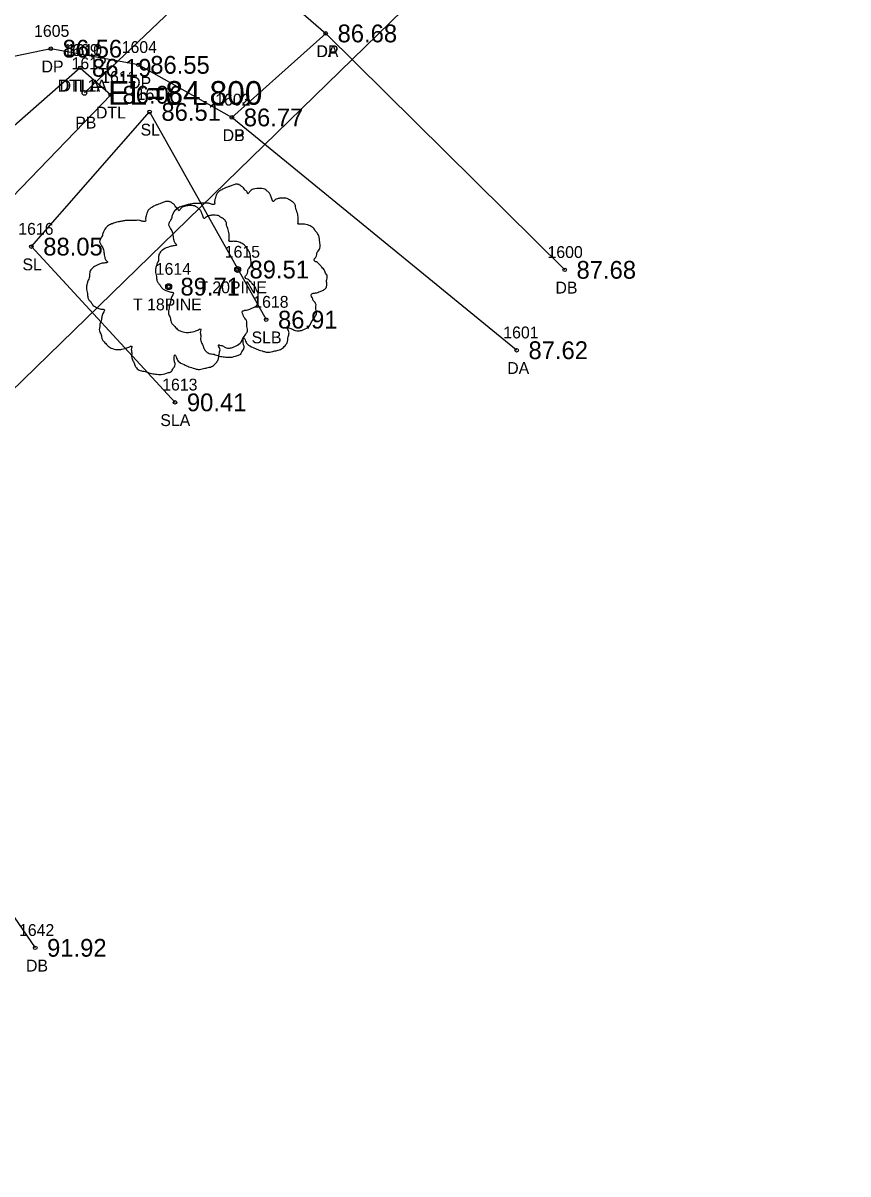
# Model space of a CAD drawing. Extents: x 2500794 to 2511032, y 910653 to 917533.
# Drawn here: x 2504844.2 to 2504913.8, y 912430.5 to 912527.6 of the extents above; entities that cross this region are included whole.
import ezdxf

# ---------------------------------------------------------------- set-up
doc = ezdxf.new("R2010")
doc.units = 0
for name, color, linetype in [('RD_EX_DR_Pipe', 7, 'Continuous'), ('RD_EX_DR_Pipe_txCode', 7, 'Continuous'), ('RD_EX_Driveway', 7, 'Continuous'), ('RD_EX_Driveway_txCode', 7, 'Continuous'), ('RD_EX_H2O_txCode', 7, 'Continuous'), ('RD_EX_RW', 7, 'Continuous'), ('RD_EX_TX_Driveway_ELEV', 7, 'Continuous'), ('RD_EX_TX_H2O_ELEV', 7, 'Continuous'), ('RD_EX_TX_VEG_ELEV', 7, 'Continuous'), ('RD_EX_VEG', 7, 'Continuous'), ('RD_EX_VEG_txCode', 7, 'Continuous'), ('RD_SMD_Locator', 7, 'Continuous'), ('RD_TX_Pipe_ElevEX', 7, 'Continuous')]:
    doc.layers.add(name, color=color, linetype=linetype)

msp = doc.modelspace()

# ---------------------------------------------------------------- linework, layer by layer
at = {"layer": 'RD_EX_DR_Pipe'}
msp.add_line((2504864.709, 912536.271), (2504849.414, 912521.689), dxfattribs=at)
at = {"layer": 'RD_EX_Driveway'}
for p, q in [((2504869.768, 912526.71), (2504889.926, 912506.766)), ((2504885.872, 912499.982), (2504861.854, 912519.624)), ((2504835.044, 912464.414), (2504845.262, 912449.566))]:
    msp.add_line(p, q, dxfattribs=at)
msp.add_lwpolyline([(2504858.984, 912543.75), (2504859.029, 912538.328), (2504862.415, 912533.12), (2504869.768, 912526.71), (2504861.854, 912519.624), (2504853.965, 912524.059), (2504846.572, 912525.423), (2504838.286, 912523.698)], dxfattribs=at)
at = {"layer": 'RD_EX_H2O_txCode'}
msp.add_line((2504849.048, 912523.81), (2504814.012, 912493.075), dxfattribs=at)
msp.add_lwpolyline([(2504849.048, 912523.81), (2504851.627, 912521.534), (2504818.417, 912487.12), (2504814.012, 912493.075)], dxfattribs=at)
at = {"layer": 'RD_EX_RW'}
msp.add_line((2503981.182, 911658.034), (2505252.676, 912894.806), dxfattribs=at)
at = {"layer": 'RD_EX_VEG'}
msp.add_lwpolyline([(2504857.057, 912495.585), (2504844.938, 912508.724), (2504854.906, 912520.09), (2504864.743, 912502.565)], dxfattribs=at)
for centre, radius in [((2504862.337, 912506.79), 0.25), ((2504862.325, 912506.771), 0.0001), ((2504856.515, 912505.346), 0.25), ((2504856.502, 912505.327), 0.0001)]:
    msp.add_circle(centre, radius, dxfattribs=at)
for points in [[(2504862.469, 912513.958), (2504862.169, 912513.983), (2504861.844, 912513.883), (2504861.595, 912513.783), (2504861.37, 912513.708), (2504861.145, 912513.608), (2504860.845, 912513.433), (2504860.62, 912513.233), (2504860.495, 912512.983), (2504860.445, 912512.758), (2504860.395, 912512.483), (2504860.395, 912512.308), (2504860.27, 912512.283), (2504860.12, 912512.308), (2504859.87, 912512.383), (2504859.62, 912512.383), (2504859.37, 912512.383), (2504859.021, 912512.358), (2504858.671, 912512.358), (2504858.396, 912512.308), (2504858.071, 912512.258), (2504857.696, 912512.133), (2504857.346, 912512.008), (2504857.047, 912511.758), (2504856.797, 912511.284), (2504856.672, 912510.934), (2504856.522, 912510.684), (2504856.672, 912510.234), (2504856.847, 912509.884), (2504856.872, 912509.684), (2504856.947, 912509.26), (2504857.047, 912509.035), (2504857.171, 912508.835), (2504857.097, 912508.81), (2504856.722, 912508.76), (2504856.422, 912508.66), (2504855.997, 912508.435), (2504855.772, 912508.21), (2504855.672, 912507.885), (2504855.647, 912507.535), (2504855.547, 912507.335), (2504855.472, 912507.061), (2504855.447, 912506.986), (2504855.397, 912506.661), (2504855.497, 912506.211), (2504855.522, 912505.861), (2504855.647, 912505.636), (2504855.797, 912505.461), (2504855.972, 912505.211), (2504856.372, 912504.986), (2504856.697, 912504.886), (2504856.897, 912504.862), (2504856.722, 912504.362), (2504856.672, 912504.012), (2504856.547, 912503.612), (2504856.547, 912503.537), (2504856.497, 912503.062), (2504856.647, 912502.737), (2504856.722, 912502.363), (2504856.897, 912502.138), (2504857.171, 912501.838), (2504857.496, 912501.613), (2504857.996, 912501.488), (2504858.396, 912501.513), (2504858.971, 912501.688), (2504859.221, 912501.763), (2504859.196, 912501.588), (2504859.221, 912501.213), (2504859.221, 912500.788), (2504859.37, 912500.463), (2504859.47, 912500.189), (2504859.62, 912499.939), (2504859.945, 912499.714), (2504860.345, 912499.639), (2504860.77, 912499.489), (2504861.22, 912499.414), (2504861.719, 912499.389), (2504862.319, 912499.539), (2504862.594, 912499.664), (2504862.694, 912499.839), (2504862.894, 912500.214), (2504862.844, 912500.438), (2504862.869, 912501.038), (2504862.969, 912500.863), (2504863.144, 912500.513), (2504863.644, 912500.214), (2504864.043, 912500.039), (2504864.518, 912499.889), (2504864.818, 912499.814), (2504865.293, 912499.889), (2504865.668, 912499.964), (2504866.043, 912500.089), (2504866.342, 912500.363), (2504866.517, 912500.638), (2504866.567, 912500.913), (2504866.642, 912501.288), (2504866.692, 912501.463)], [(2504866.692, 912501.463), (2504866.617, 912501.638), (2504866.567, 912501.888), (2504866.642, 912501.863), (2504866.817, 912501.813), (2504867.092, 912501.688), (2504867.317, 912501.613), (2504867.642, 912501.638), (2504867.917, 912501.738), (2504868.367, 912502.013), (2504868.641, 912502.488), (2504868.916, 912502.887), (2504868.991, 912503.212), (2504868.941, 912503.437), (2504868.916, 912503.937), (2504868.716, 912504.187), (2504868.666, 912504.312), (2504868.566, 912504.712), (2504868.641, 912504.762), (2504868.916, 912504.812), (2504869.291, 912504.936), (2504869.566, 912505.061), (2504869.791, 912505.236), (2504869.866, 912505.461), (2504869.841, 912505.861), (2504869.891, 912506.261), (2504869.816, 912506.411), (2504869.716, 912506.561), (2504869.641, 912506.761), (2504869.491, 912506.911), (2504869.391, 912507.061), (2504869.291, 912507.16), (2504869.166, 912507.31), (2504868.991, 912507.435), (2504868.841, 912507.485), (2504868.791, 912507.635), (2504868.941, 912507.835), (2504868.991, 912507.935), (2504869.016, 912508.16), (2504869.241, 912508.51), (2504869.291, 912508.91), (2504869.241, 912509.335), (2504869.191, 912509.609), (2504869.041, 912509.884), (2504868.841, 912510.134), (2504868.716, 912510.309), (2504868.541, 912510.434), (2504868.217, 912510.559), (2504867.967, 912510.609), (2504867.617, 912510.609), (2504867.417, 912510.659), (2504867.442, 912510.709), (2504867.442, 912510.859), (2504867.442, 912511.134), (2504867.367, 912511.584), (2504867.217, 912512.083), (2504867.217, 912512.108), (2504867.117, 912512.358), (2504866.892, 912512.558), (2504866.717, 912512.658), (2504866.517, 912512.783), (2504866.267, 912512.808), (2504865.968, 912512.808), (2504865.693, 912512.758), (2504865.493, 912512.658), (2504865.318, 912512.533), (2504865.243, 912512.683), (2504865.143, 912512.983), (2504865.093, 912513.133), (2504864.943, 912513.308), (2504864.718, 912513.508), (2504864.268, 912513.633), (2504863.644, 912513.558), (2504863.344, 912513.358), (2504863.194, 912513.183), (2504863.144, 912513.308), (2504862.944, 912513.508), (2504862.844, 912513.683), (2504862.669, 912513.808), (2504862.519, 912513.908), (2504862.419, 912513.958)], [(2504856.646, 912512.513), (2504856.347, 912512.538), (2504856.022, 912512.438), (2504855.772, 912512.338), (2504855.547, 912512.263), (2504855.322, 912512.163), (2504855.022, 912511.989), (2504854.797, 912511.789), (2504854.672, 912511.539), (2504854.622, 912511.314), (2504854.572, 912511.039), (2504854.572, 912510.864), (2504854.447, 912510.839), (2504854.297, 912510.864), (2504854.048, 912510.939), (2504853.798, 912510.939), (2504853.548, 912510.939), (2504853.198, 912510.914), (2504852.848, 912510.914), (2504852.573, 912510.864), (2504852.248, 912510.814), (2504851.874, 912510.689), (2504851.524, 912510.564), (2504851.224, 912510.314), (2504850.974, 912509.84), (2504850.849, 912509.49), (2504850.699, 912509.24), (2504850.849, 912508.79), (2504851.024, 912508.44), (2504851.049, 912508.24), (2504851.124, 912507.815), (2504851.224, 912507.591), (2504851.349, 912507.391), (2504851.274, 912507.366), (2504850.899, 912507.316), (2504850.599, 912507.216), (2504850.174, 912506.991), (2504849.949, 912506.766), (2504849.849, 912506.441), (2504849.824, 912506.091), (2504849.725, 912505.891), (2504849.65, 912505.616), (2504849.625, 912505.541), (2504849.575, 912505.217), (2504849.675, 912504.767), (2504849.7, 912504.417), (2504849.824, 912504.192), (2504849.974, 912504.017), (2504850.149, 912503.767), (2504850.549, 912503.542), (2504850.874, 912503.442), (2504851.074, 912503.417), (2504850.899, 912502.918), (2504850.849, 912502.568), (2504850.724, 912502.168), (2504850.724, 912502.093), (2504850.674, 912501.618), (2504850.824, 912501.293), (2504850.899, 912500.918), (2504851.074, 912500.694), (2504851.349, 912500.394), (2504851.674, 912500.169), (2504852.173, 912500.044), (2504852.573, 912500.069), (2504853.148, 912500.244), (2504853.398, 912500.319), (2504853.373, 912500.144), (2504853.398, 912499.769), (2504853.398, 912499.344), (2504853.548, 912499.019), (2504853.648, 912498.744), (2504853.798, 912498.494), (2504854.123, 912498.27), (2504854.522, 912498.195), (2504854.947, 912498.045), (2504855.397, 912497.97), (2504855.897, 912497.945), (2504856.497, 912498.095), (2504856.771, 912498.22), (2504856.871, 912498.395), (2504857.071, 912498.769), (2504857.021, 912498.994), (2504857.046, 912499.594), (2504857.146, 912499.419), (2504857.321, 912499.069), (2504857.821, 912498.769), (2504858.221, 912498.594), (2504858.696, 912498.444), (2504858.995, 912498.37), (2504859.47, 912498.444), (2504859.845, 912498.519), (2504860.22, 912498.644), (2504860.52, 912498.919), (2504860.695, 912499.194), (2504860.745, 912499.469), (2504860.82, 912499.844), (2504860.87, 912500.019)], [(2504860.87, 912500.019), (2504860.795, 912500.194), (2504860.745, 912500.444), (2504860.82, 912500.419), (2504860.995, 912500.369), (2504861.269, 912500.244), (2504861.494, 912500.169), (2504861.819, 912500.194), (2504862.094, 912500.294), (2504862.544, 912500.569), (2504862.819, 912501.043), (2504863.094, 912501.443), (2504863.169, 912501.768), (2504863.119, 912501.993), (2504863.094, 912502.493), (2504862.894, 912502.743), (2504862.844, 912502.868), (2504862.744, 912503.267), (2504862.819, 912503.317), (2504863.094, 912503.367), (2504863.468, 912503.492), (2504863.743, 912503.617), (2504863.968, 912503.792), (2504864.043, 912504.017), (2504864.018, 912504.417), (2504864.068, 912504.817), (2504863.993, 912504.967), (2504863.893, 912505.117), (2504863.818, 912505.317), (2504863.668, 912505.466), (2504863.568, 912505.616), (2504863.468, 912505.716), (2504863.344, 912505.866), (2504863.169, 912505.991), (2504863.019, 912506.041), (2504862.969, 912506.191), (2504863.119, 912506.391), (2504863.169, 912506.491), (2504863.194, 912506.716), (2504863.419, 912507.066), (2504863.468, 912507.466), (2504863.419, 912507.89), (2504863.369, 912508.165), (2504863.219, 912508.44), (2504863.019, 912508.69), (2504862.894, 912508.865), (2504862.719, 912508.99), (2504862.394, 912509.115), (2504862.144, 912509.165), (2504861.794, 912509.165), (2504861.594, 912509.215), (2504861.619, 912509.265), (2504861.619, 912509.415), (2504861.619, 912509.69), (2504861.544, 912510.139), (2504861.394, 912510.639), (2504861.394, 912510.664), (2504861.294, 912510.914), (2504861.07, 912511.114), (2504860.895, 912511.214), (2504860.695, 912511.339), (2504860.445, 912511.364), (2504860.145, 912511.364), (2504859.87, 912511.314), (2504859.67, 912511.214), (2504859.495, 912511.089), (2504859.42, 912511.239), (2504859.32, 912511.539), (2504859.27, 912511.689), (2504859.12, 912511.864), (2504858.896, 912512.064), (2504858.446, 912512.188), (2504857.821, 912512.114), (2504857.521, 912511.914), (2504857.371, 912511.739), (2504857.321, 912511.864), (2504857.121, 912512.064), (2504857.021, 912512.238), (2504856.846, 912512.363), (2504856.696, 912512.463), (2504856.596, 912512.513)]]:
    msp.add_spline(points, degree=3, dxfattribs=at)
at = {"layer": 'RD_SMD_Locator'}
for centre, radius in [((2504869.768, 912526.71), 0.15), ((2504869.768, 912526.71), 0.15), ((2504846.572, 912525.423), 0.15), ((2504849.048, 912523.81), 0.15), ((2504849.048, 912523.81), 0.15), ((2504853.965, 912524.059), 0.15), ((2504849.414, 912521.689), 0.2), ((2504851.627, 912521.534), 0.15), ((2504854.906, 912520.09), 0.15), ((2504861.854, 912519.624), 0.15), ((2504861.854, 912519.624), 0.15), ((2504844.938, 912508.724), 0.15), ((2504862.337, 912506.79), 0.15), ((2504889.926, 912506.766), 0.15), ((2504856.515, 912505.346), 0.15), ((2504864.743, 912502.565), 0.15), ((2504885.872, 912499.982), 0.15), ((2504857.057, 912495.585), 0.15), ((2504845.262, 912449.566), 0.15)]:
    msp.add_circle(centre, radius, dxfattribs=at)

# ---------------------------------------------------------------- texts
at = {"layer": 'RD_EX_DR_Pipe_txCode'}
for s, p in [('1612', (2504848.327, 912523.689)), ('PB', (2504848.634, 912518.689))]:
    msp.add_text(s, height=1, dxfattribs=at).set_placement(p)
at = {"layer": 'RD_EX_Driveway_txCode'}
for s, p in [('1605', (2504845.163, 912526.423)), ('1604', (2504852.555, 912525.059)), ('DA', (2504868.973, 912524.71)), ('DP', (2504868.989, 912524.71)), ('DP', (2504845.792, 912523.423)), ('DP', (2504853.185, 912522.059)), ('1602', (2504860.444, 912520.624)), ('1603', (2504860.444, 912520.624)), ('DB', (2504861.074, 912517.624)), ('DP', (2504861.074, 912517.624)), ('1600', (2504888.477, 912507.766)), ('DB', (2504889.146, 912504.766)), ('1601', (2504884.746, 912500.982)), ('DA', (2504885.077, 912497.982)), ('1642', (2504843.892, 912450.566)), ('DB', (2504844.483, 912447.566))]:
    msp.add_text(s, height=1, dxfattribs=at).set_placement(p)
at = {"layer": 'RD_EX_H2O_txCode'}
for s, p in [('1609', (2504847.638, 912524.81)), ('1610', (2504847.922, 912524.81)), ('1611', (2504850.824, 912522.534)), ('DTL1A', (2504847.15, 912521.81)), ('DTLA', (2504847.316, 912521.81)), ('DTL', (2504850.383, 912519.534))]:
    msp.add_text(s, height=1, dxfattribs=at).set_placement(p)
at = {"layer": 'RD_EX_TX_Driveway_ELEV'}
for s, p in [('86.68', (2504870.768, 912525.96)), ('86.68', (2504870.768, 912525.96)), ('86.56', (2504847.572, 912524.673)), ('86.55', (2504854.965, 912523.309)), ('86.77', (2504862.854, 912518.874)), ('86.77', (2504862.854, 912518.874)), ('87.68', (2504890.926, 912506.016)), ('87.62', (2504886.872, 912499.232)), ('91.92', (2504846.262, 912448.816))]:
    msp.add_text(s, height=1.5, dxfattribs=at).set_placement(p)
at = {"layer": 'RD_EX_TX_H2O_ELEV'}
for s, p in [('86.19', (2504850.048, 912523.06)), ('86.19', (2504850.048, 912523.06)), ('86.06', (2504852.627, 912520.784))]:
    msp.add_text(s, height=1.5, dxfattribs=at).set_placement(p)
at = {"layer": 'RD_EX_TX_VEG_ELEV'}
for s, p in [('86.51', (2504855.906, 912519.34)), ('88.05', (2504845.938, 912507.974)), ('89.51', (2504863.337, 912506.04)), ('89.71', (2504857.515, 912504.596)), ('86.91', (2504865.743, 912501.815)), ('90.41', (2504858.057, 912494.835))]:
    msp.add_text(s, height=1.5, dxfattribs=at).set_placement(p)
at = {"layer": 'RD_EX_VEG_txCode'}
for s, p in [('1617', (2504853.819, 912521.09)), ('SL', (2504854.15, 912518.09)), ('1616', (2504843.828, 912509.724)), ('1615', (2504861.251, 912507.79)), ('SL', (2504844.182, 912506.724)), ('1614', (2504855.428, 912506.346)), ('T 20PINE', (2504859.01, 912504.79)), ('1618', (2504863.656, 912503.565)), ('T 18PINE', (2504853.511, 912503.346)), ('SLB', (2504863.514, 912500.565)), ('1613', (2504855.971, 912496.585)), ('SLA', (2504855.813, 912493.585))]:
    msp.add_text(s, height=1, dxfattribs=at).set_placement(p)
at = {"layer": 'RD_TX_Pipe_ElevEX'}
msp.add_text('EL=84.800', height=2, dxfattribs=at).set_placement((2504851.414, 912520.689))

doc.saveas('drawing.dxf')
